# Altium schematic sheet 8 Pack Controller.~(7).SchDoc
size B; PageSetup: Record=PageOptions|CenterHorizontal=True|CenterVertical=True|PrintScale=1.09|XCorrection=1.00|YCorrection=1.00|PrintKind=0|BorderSize=5000000|LeftOffset=0|BottomOffset=0|Orientation=2|PaperLength=1000|PaperWidth=1000|Scale=100|PaperSource=15|PrintQuality=600|MediaType=1|DitherType=10|PaperKind=11x17|PrintScaleMode=1
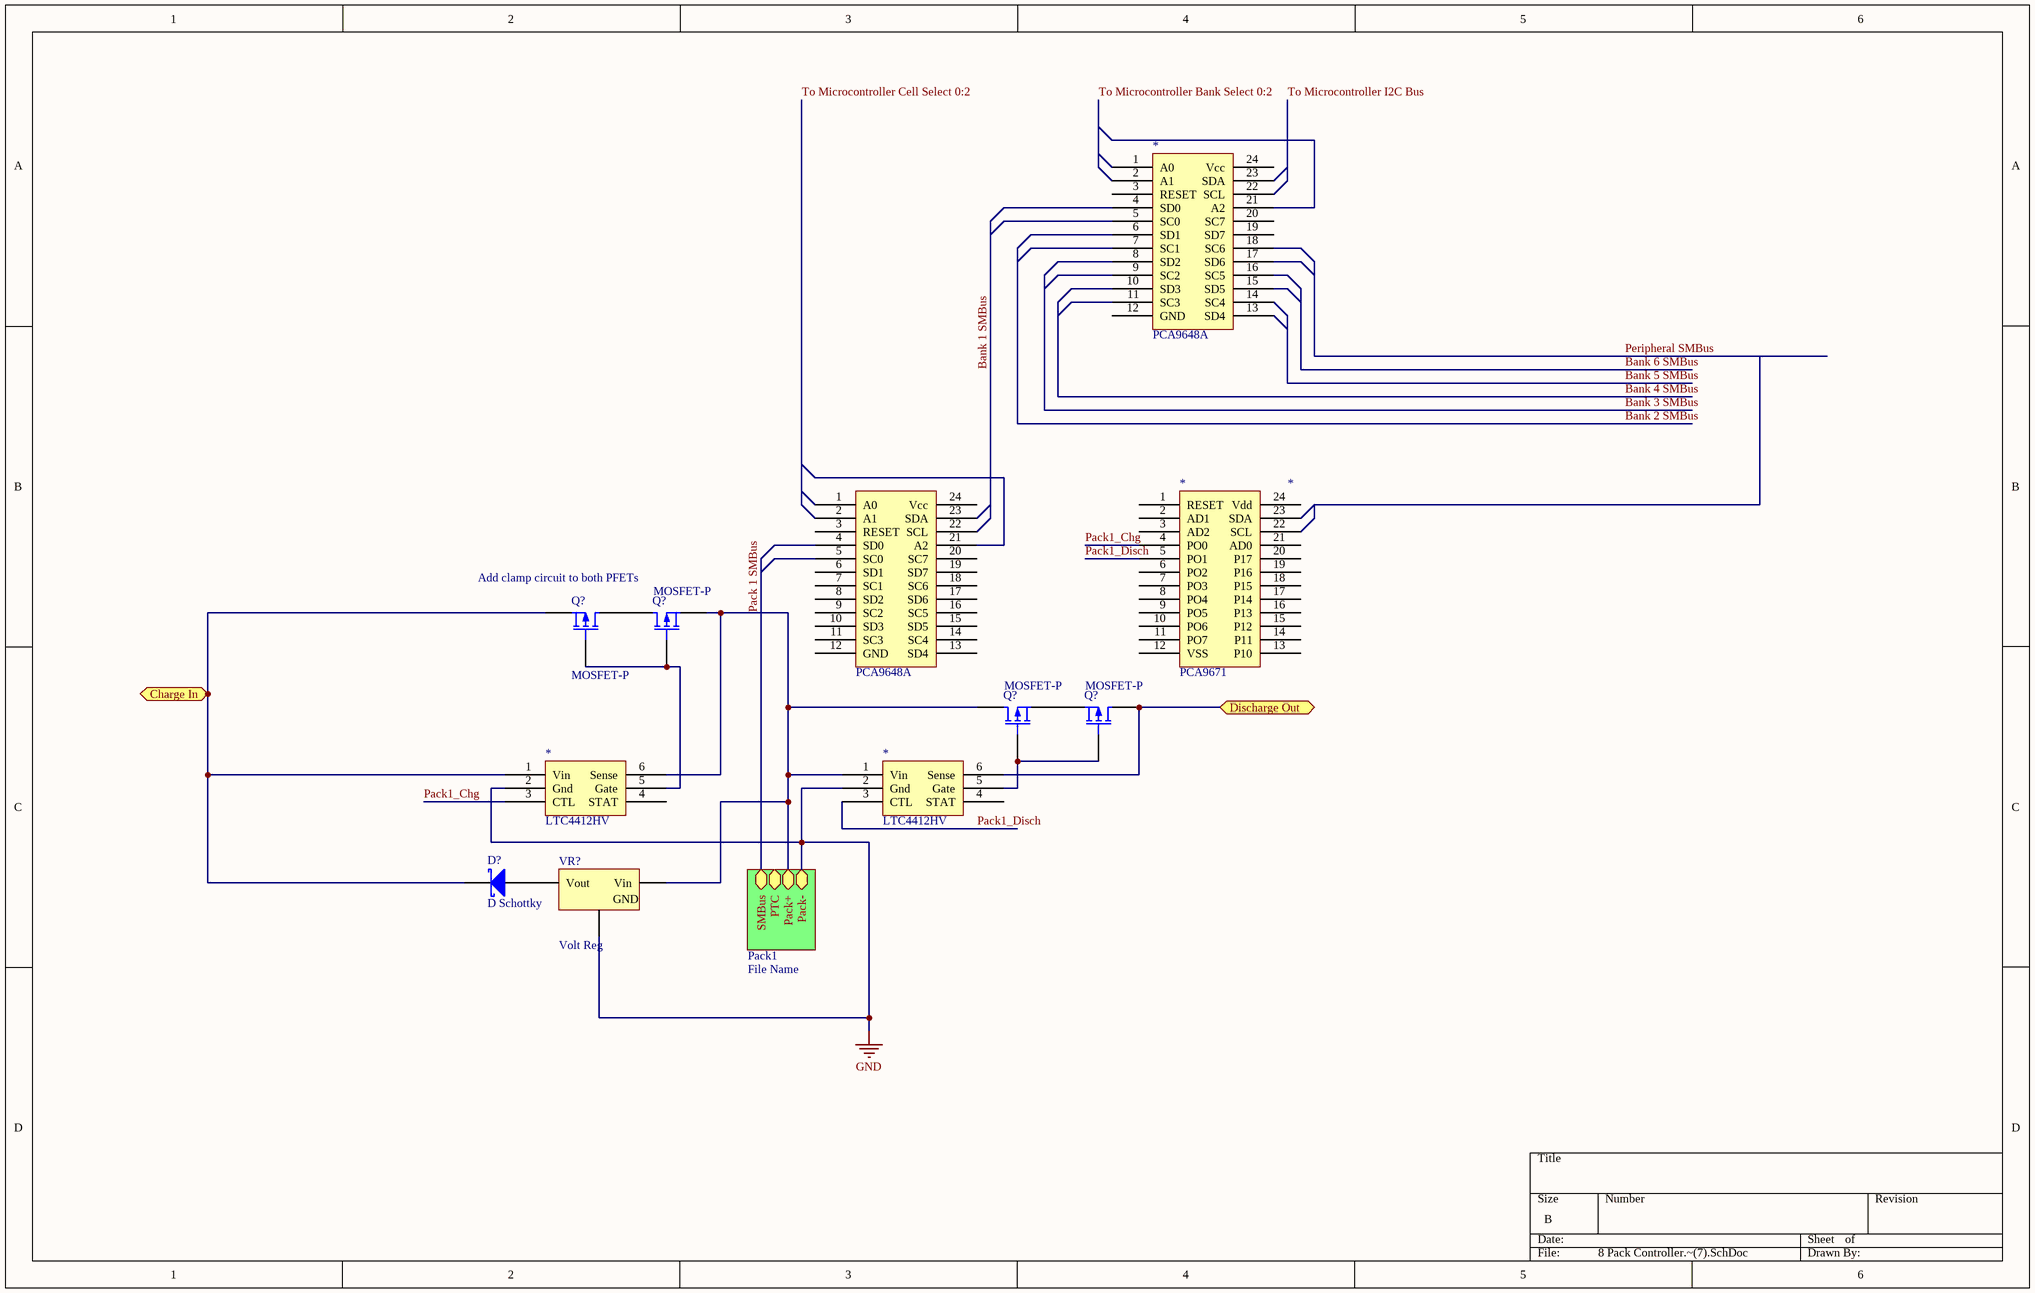
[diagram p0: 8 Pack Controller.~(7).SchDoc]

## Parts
(Parts that share a designator on the sheet are numbered #1, #2 ... from top to bottom, then left to right.)
*#1  PCA9648A
*#2  PCA9648A
*#3  PCA9671
*#4  LTC4412HV
*#5  LTC4412HV
D?  D Schottky  [DSO-C2/X2.3]
Q?#1  MOSFET-P  [BCY-W3/B.8]
Q?#2  MOSFET-P  [BCY-W3/B.8]
Q?#3  MOSFET-P  [BCY-W3/B.8]
Q?#4  MOSFET-P  [BCY-W3/B.8]
VR?  Volt Reg  [TO254P1510-3_4N]

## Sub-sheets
Pack1 = File Name: SMBus, PTC, Pack+, Pack-

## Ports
Charge In, Discharge Out

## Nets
GND: *#4.2(Gnd) *#5.2(Gnd) VR?.2(GND) ; sheet Pack1/Pack-
Charge In: *#4.1(Vin) D?.2(K) Q?#1.3(S) ; port Charge In
Discharge Out: *#5.6(Sense) Q?#4.1(D) ; port Discharge Out
Pack1_Chg: *#3.4(PO0) *#4.3(CTL)
Pack1_Disch: *#3.5(PO1) *#5.3(CTL)
Pack 1 SMBus: *#4.6(Sense) *#5.1(Vin) Q?#2.3(S) Q?#3.1(D) VR?.1(Vin) ; sheet Pack1/Pack+
Net*#4_5: *#4.5(Gate) Q?#1.2(G) Q?#2.2(G)
Net*#5_5: *#5.5(Gate) Q?#3.2(G) Q?#4.2(G)
NetD?_1: D?.1(A) VR?.3(Vout)
NetQ?#1_1: Q?#1.1(D) Q?#2.1(D)
NetQ?#3_3: Q?#3.3(S) Q?#4.3(S)

Not connected (* = marked no-connect by the designer): *#1 1(A0) 2(A1) 3(RESET) 4(SD0) 5(SC0) 6(SD1) 7(SC1) 8(SD2) 9(SC2) 10(SD3) 11(SC3) 12(GND) 13(SD4) 14(SC4) 15(SD5) 16(SC5) 17(SD6) 18(SC6) 19(SD7) 20(SC7) 21(A2) 22(SCL) 23(SDA) 24(Vcc); *#2 1(A0) 2(A1) 3(RESET) 4(SD0) 5(SC0) 6(SD1) 7(SC1) 8(SD2) 9(SC2) 10(SD3) 11(SC3) 12(GND) 13(SD4) 14(SC4) 15(SD5) 16(SC5) 17(SD6) 18(SC6) 19(SD7) 20(SC7) 21(A2) 22(SCL) 23(SDA) 24(Vcc); *#3 1(RESET) 2(AD1) 3(AD2) 6(PO2) 7(PO3) 8(PO4) 9(PO5) 10(PO6) 11(PO7) 12(VSS) 13(P10) 14(P11) 15(P12) 16(P13) 17(P14) 18(P15) 19(P16) 20(P17) 21(AD0) 22(SCL) 23(SDA) 24(Vdd); *#4 4(STAT); *#5 4(STAT)

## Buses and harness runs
bus Bank 1 SMBus
bus Bank 2 SMBus
bus Bank 3 SMBus
bus Bank 4 SMBus
bus Bank 5 SMBus
bus Bank 6 SMBus
bus Peripheral SMBus
bus To Microcontroller Bank Select 0:2
bus To Microcontroller Cell Select 0:2
bus To Microcontroller I2C Bus

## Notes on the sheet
- (near Q?#2) Add clamp circuit to both PFETs

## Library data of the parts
D? = D Schottky: Schottky Diode
Q?#1-Q?#4 = MOSFET-P: P-Channel MOSFET
VR? = Volt Reg: Voltage Regulator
